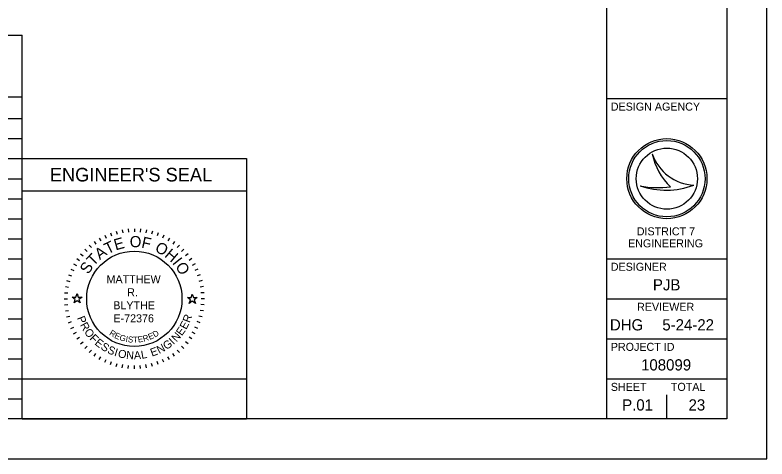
# Model space of a CAD drawing. Extents: x -1.1 to 34, y 0 to 29.8.
# Drawn here: x 24.61 to 34, y 0 to 5.54 of the extents above; entities that cross this region are included whole.
import ezdxf

# ---------------------------------------------------------------- set-up
doc = ezdxf.new("R2010")
doc.units = 0
for name, color, linetype in [('SH_Border', 7, 'Continuous'), ('SH_Cut_Line', 7, 'Continuous'), ('SH_Data', 7, 'Continuous'), ('SH_Text', 7, 'Continuous')]:
    doc.layers.add(name, color=color, linetype=linetype)

msp = doc.modelspace()

# ---------------------------------------------------------------- linework, layer by layer
at = {"layer": 'SH_Border'}
for p, q in [((32, 0.5), (32, 21.5)), ((32, 4.5), (33.5, 4.5)), ((32, 2.5), (33.5, 2.5)), ((32, 2), (33.5, 2)), ((32, 1.5), (33.5, 1.5)), ((32, 1), (33.5, 1))]:
    msp.add_line(p, q, dxfattribs=at)
msp.add_lwpolyline([(1.5, 21.5), (33.5, 21.5), (33.5, 0.5), (1.5, 0.5)], close=True, dxfattribs=at)
at = {"layer": 'SH_Cut_Line'}
msp.add_lwpolyline([(0, 0), (34, 0), (34, 22), (0, 22)], close=True, dxfattribs=at)
at = {"layer": 'SH_Data'}
for p, q in [((11.25, 5.2917), (24.7, 5.2917)), ((24.7, 0.5), (24.7, 5.2917)), ((11.25, 4.5209), (24.7, 4.5209)), ((11.25, 4.25), (24.7, 4.25)), ((11.25, 4), (24.7, 4)), ((32.5674, 3.8096), (32.5675, 3.8096)), ((11.25, 3.75), (24.7, 3.75)), ((24.7, 0.5), (24.7, 3.75)), ((24.7, 3.75), (27.5, 3.75)), ((27.5, 3.75), (27.5, 0.5)), ((11.25, 3.5), (24.7, 3.5)), ((32.75, 3.5), (32.75, 3.5)), ((32.4172, 3.4095), (32.4172, 3.4095)), ((33.0873, 3.4185), (33.0873, 3.4185)), ((24.7, 3.35), (27.5, 3.35)), ((11.25, 3.25), (24.7, 3.25)), ((11.25, 3), (24.7, 3)), ((25.8007, 2.8222), (25.8144, 2.7846)), ((25.8735, 2.8452), (25.8839, 2.8065)), ((25.9481, 2.8617), (25.955, 2.8223)), ((26.0237, 2.8717), (26.0272, 2.8318)), ((26.1, 2.875), (26.1, 2.835)), ((26.1763, 2.8717), (26.1728, 2.8318)), ((26.2519, 2.8617), (26.245, 2.8223)), ((26.3265, 2.8452), (26.3161, 2.8065)), ((26.3993, 2.8222), (26.3856, 2.7846)), ((11.25, 2.75), (24.7, 2.75)), ((25.6625, 2.7578), (25.6825, 2.7231)), ((25.7302, 2.793), (25.7471, 2.7568)), ((26.4698, 2.793), (26.4529, 2.7568)), ((26.5375, 2.7578), (26.5175, 2.7231)), ((25.5376, 2.6703), (25.5633, 2.6396)), ((25.5981, 2.7168), (25.6211, 2.684)), ((26.6019, 2.7168), (26.5789, 2.684)), ((26.6624, 2.6703), (26.6367, 2.6396)), ((25.4297, 2.5624), (25.4604, 2.5367)), ((25.4813, 2.6187), (25.5096, 2.5904)), ((26.7187, 2.6187), (26.6904, 2.5904)), ((26.7703, 2.5624), (26.7396, 2.5367)), ((11.25, 2.5), (24.7, 2.5)), ((25.3832, 2.5019), (25.416, 2.4789)), ((26.8168, 2.5019), (26.784, 2.4789)), ((25.307, 2.3698), (25.3432, 2.3529)), ((25.3422, 2.4375), (25.3769, 2.4175)), ((26.8578, 2.4375), (26.8231, 2.4175)), ((26.893, 2.3698), (26.8568, 2.3529)), ((25.2778, 2.2993), (25.3154, 2.2856)), ((26.9222, 2.2993), (26.8846, 2.2856)), ((11.25, 2.25), (24.7, 2.25)), ((25.2548, 2.2265), (25.2935, 2.2161)), ((26.9452, 2.2265), (26.9065, 2.2161)), ((25.2283, 2.0763), (25.2682, 2.0728)), ((25.2383, 2.1519), (25.2777, 2.145)), ((26.9617, 2.1519), (26.9223, 2.145)), ((26.9717, 2.0763), (26.9318, 2.0728)), ((11.25, 2), (24.7, 2)), ((25.225, 2), (25.265, 2)), ((26.975, 2), (26.935, 2)), ((25.2283, 1.9237), (25.2682, 1.9272)), ((26.9717, 1.9237), (26.9318, 1.9272)), ((25.2383, 1.8481), (25.2777, 1.855)), ((26.9617, 1.8481), (26.9223, 1.855)), ((11.25, 1.75), (24.7, 1.75)), ((25.2548, 1.7735), (25.2935, 1.7839)), ((25.2778, 1.7007), (25.3154, 1.7144)), ((26.9222, 1.7007), (26.8846, 1.7144)), ((26.9452, 1.7735), (26.9065, 1.7839)), ((25.307, 1.6302), (25.3432, 1.6471)), ((26.893, 1.6302), (26.8568, 1.6471)), ((25.3422, 1.5625), (25.3769, 1.5825)), ((25.3832, 1.4981), (25.416, 1.5211)), ((26.8168, 1.4981), (26.784, 1.5211)), ((26.8578, 1.5625), (26.8231, 1.5825)), ((11.25, 1.5), (24.7, 1.5)), ((25.4297, 1.4376), (25.4604, 1.4633)), ((25.4813, 1.3813), (25.5096, 1.4096)), ((26.7187, 1.3813), (26.6904, 1.4096)), ((26.7703, 1.4376), (26.7396, 1.4633)), ((25.5376, 1.3297), (25.5633, 1.3604)), ((25.5981, 1.2832), (25.6211, 1.316)), ((26.6019, 1.2832), (26.5789, 1.316)), ((26.6624, 1.3297), (26.6367, 1.3604)), ((11.25, 1.25), (24.7, 1.25)), ((25.6625, 1.2422), (25.6825, 1.2769)), ((25.7302, 1.207), (25.7471, 1.2432)), ((26.4698, 1.207), (26.4529, 1.2432)), ((26.5375, 1.2422), (26.5175, 1.2769)), ((25.8007, 1.1778), (25.8144, 1.2154)), ((25.8735, 1.1548), (25.8839, 1.1935)), ((25.9481, 1.1383), (25.955, 1.1777)), ((26.0237, 1.1283), (26.0272, 1.1682)), ((26.1, 1.125), (26.1, 1.165)), ((26.1763, 1.1283), (26.1728, 1.1682)), ((26.2519, 1.1383), (26.245, 1.1777)), ((26.3265, 1.1548), (26.3161, 1.1935)), ((26.3993, 1.1778), (26.3856, 1.2154)), ((11.25, 1), (24.7, 1)), ((32.75, 0.5), (32.75, 0.8)), ((11.25, 0.75), (24.7, 0.75)), ((32.375, 0.675), (32.375, 0.675)), ((24.7, 0.5), (27.5, 0.5)), ((24.7, 0.5), (27.5, 0.5))]:
    msp.add_line(p, q, dxfattribs=at)
for points in [[(25.3236, 2.02), (25.3705, 2.02), (25.385, 2.0645), (25.3995, 2.02), (25.4464, 2.02), (25.4085, 1.9924), (25.423, 1.9478), (25.385, 1.9754), (25.347, 1.9478), (25.3615, 1.9924)], [(26.7627, 2.0146), (26.8096, 2.0146), (26.8241, 2.0591), (26.8386, 2.0146), (26.8855, 2.0146), (26.8476, 1.987), (26.8621, 1.9424), (26.8241, 1.97), (26.7861, 1.9424), (26.8006, 1.987)], [(24.7, 0.5), (24.7, 1), (27.5, 1), (27.5, 0.5)]]:
    msp.add_lwpolyline(points, close=True, dxfattribs=at)
for centre, radius in [((32.75, 3.5), 0.5), ((32.75, 3.5), 0.4768), ((32.75, 3.5), 0.4768), ((32.75, 3.5), 0.3822), ((26.1, 2), 0.595)]:
    msp.add_circle(centre, radius, dxfattribs=at)
for centre, radius, start, end in [((33.1159, 3.9976), 0.5798, 198.92567, 198.93195), ((33.3467, 3.9701), 0.7956, 191.63793, 191.64215), ((33.1159, 3.9976), 0.5798, 198.93195, 267.16574), ((33.3467, 3.9701), 0.7956, 191.64215, 226.09467), ((32.7394, 4.37), 1.0131, 251.45764, 290.08324), ((32.648, 4.6543), 1.2661, 259.49639, 259.49952), ((32.7394, 4.37), 1.0131, 251.45274, 251.45764), ((32.648, 4.6543), 1.2661, 259.49952, 276.66723)]:
    msp.add_arc(centre, radius, start, end, dxfattribs=at)

# ---------------------------------------------------------------- texts
for s, height, p in [('DESIGN AGENCY', 0.1, (32.05, 4.35)), ("ENGINEER'S SEAL", 0.17, (25.0448, 3.465)), ('DESIGNER', 0.1, (32.05, 2.35)), ('MATTHEW', 0.1, (25.7528, 2.1938)), ('PJB', 0.14, (32.5758, 2.105)), ('R. ', 0.1, (26.0107, 2.0313)), ('BLYTHE', 0.1, (25.8371, 1.8688)), ('REVIEWER', 0.1, (32.3783, 1.85)), ('E-72376', 0.1, (25.8391, 1.7063)), ('DHG', 0.14, (32.0388, 1.605)), ('5-24-22', 0.14, (32.6932, 1.605)), ('PROJECT ID', 0.1, (32.05, 1.35)), ('108099', 0.14, (32.4281, 1.105)), ('SHEET', 0.1, (32.05, 0.85)), ('TOTAL', 0.1, (32.8, 0.85)), ('P.01', 0.14, (32.1918, 0.605)), ('23', 0.14, (33.0207, 0.605))]:
    msp.add_text(s, height=height, dxfattribs=at).set_placement(p)
for s, height, rotation, p in [('T', 0.14, 25.71674, (25.7661, 2.554)), ('E', 0.14, 15.75706, (25.8669, 2.6034)), ('O', 0.14, 359.78119, (26.042, 2.6442)), ('F', 0.14, 347.43619, (26.1811, 2.6417)), ('A', 0.14, 36.47472, (25.6685, 2.4819)), ('O', 0.14, 332.25863, (26.3463, 2.5981)), ('T', 0.14, 46.4344, (25.5917, 2.4)), ('H', 0.14, 319.91363, (26.4684, 2.5316)), ('S', 0.14, 57.19238, (25.526, 2.2981)), ('I', 0.14, 308.36695, (26.5674, 2.4471)), ('O', 0.14, 303.14906, (26.6061, 2.4028)), ('P', 0.1, 291.49398, (25.3823, 1.7619)), ('R', 0.1, 69.23216, (26.7913, 1.6936)), ('R', 0.1, 298.73106, (25.4181, 1.6733)), ('E', 0.1, 61.99508, (26.7472, 1.609)), ('O', 0.1, 306.46664, (25.4682, 1.5845)), ('R', 0.075, 327.82385, (25.7801, 1.554)), ('D', 0.075, 31.46601, (26.355, 1.5136)), ('E', 0.1, 54.75801, (26.6928, 1.5306)), ('F', 0.1, 314.7068, (25.5343, 1.4983)), ('E', 0.1, 321.43929, (25.597, 1.4354)), ('E', 0.075, 337.77772, (25.8439, 1.5128)), ('G', 0.075, 344.27273, (25.9082, 1.4848)), ('I', 0.075, 350.64643, (25.9868, 1.4634)), ('S', 0.075, 353.78581, (26.0155, 1.4581)), ('T', 0.075, 3.00609, (26.0852, 1.4505)), ('E', 0.075, 8.98261, (26.1492, 1.453)), ('R', 0.075, 17.68363, (26.2187, 1.4627)), ('E', 0.075, 23.30524, (26.2909, 1.4856)), ('I', 0.1, 43.28703, (26.5876, 1.4221)), ('N', 0.1, 47.02243, (26.6242, 1.455)), ('S', 0.1, 328.67637, (25.6722, 1.3766)), ('S', 0.1, 335.91345, (25.7541, 1.3276)), ('N', 0.1, 27.31129, (26.4097, 1.3102)), ('G', 0.1, 35.04687, (26.4997, 1.3581)), ('I', 0.1, 343.15053, (25.8416, 1.2894)), ('O', 0.1, 346.88592, (25.8884, 1.2741)), ('N', 0.1, 355.12608, (25.9946, 1.2512)), ('A', 0.1, 2.86166, (26.0964, 1.2439)), ('L', 0.1, 10.09874, (26.1917, 1.2494)), ('E', 0.1, 20.07421, (26.3203, 1.2767))]:
    msp.add_text(s, height=height, rotation=rotation, dxfattribs=at).set_placement(p)
at = {"layer": 'SH_Text'}
for s, p in [('DISTRICT 7', (32.374, 2.7924)), ('ENGINEERING', (32.2652, 2.6424))]:
    msp.add_text(s, height=0.1, dxfattribs=at).set_placement(p)

doc.saveas('drawing.dxf')
